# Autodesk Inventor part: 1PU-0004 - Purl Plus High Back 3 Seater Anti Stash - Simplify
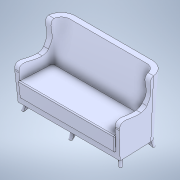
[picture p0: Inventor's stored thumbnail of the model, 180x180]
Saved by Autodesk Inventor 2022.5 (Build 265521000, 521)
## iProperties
Created: 2025-09
Part Number: 1PU-0004 - Purl Plus High Back 3 Seater Anti Stash - Simplify
Material: Generic
Document SubType Name: Modeling
Designer: Mark.Glazzard
Density: 1 g/cm^3
Appearance: Default
Author: Mark.Glazzard
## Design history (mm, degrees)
derived "1PU-0004 - Purl Plus High Back 3 Seater Anti Stash.iam"
body "Solid1"
node "1PU-0004 - BEECH FEET.ipt:1"
node "1PU-0004 - BEECH FEET.ipt:2"
body "Solid2"
node "1PU-0004 - BEECH FEET.ipt:3"
body "Solid3"
node "1PU-0004 - BEECH FEET.ipt:4"
body "Solid4"
node "1PU-0004 - FR BLACK LINING FABRIC - 2SEATER.ipt:1"
body "Solid5"
node "1PU-0004 - Upholstery 2.ipt:1"
body "Solid6"
node "1PU-0004 - Upholstery 1.ipt:1"
body "Solid7"
node "1PU-0004 - BEECH FEET.ipt:5"
body "Solid8"
node "1PU-0004 - BEECH FEET.ipt:6"
body "Solid9"
